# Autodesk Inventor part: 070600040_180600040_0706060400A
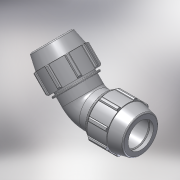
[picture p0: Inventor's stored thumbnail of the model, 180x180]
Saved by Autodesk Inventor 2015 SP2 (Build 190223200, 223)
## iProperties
Created: 2017-02
Part Number: 070600040_180600040_0706060400A
Material: PVC-Piping
Description: PLASSON 45° ELBOW 40-40
Document SubType Name: Modeling
Designer: KIM
Mass: 92.6774 g
Surface Area: 199.44 cm^2
Volume: 66.1981 cm^3
Density: 1.4 g/cm^3
Appearance: Smooth - White
Author: KIM
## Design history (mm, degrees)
derived "07060.ipt"
feature "Solid1::07060.ipt"
tag "TaggingFeature1"
body "Solid1"
other parameters: "d4" = 8.25, "d5" = 24.75, "d7" = 82, "d9" = 14.14286, "d11" = 3.3, "d13" = 120 deg, "d15" = 12 deg, "d16" = 71.34, "d18" = 2, "d19" = 35 deg, "d20" = 17.5 deg, "d21" = 76.26, "d23" = 0, "d25" = 360 deg, "d27" = 1.64, "d33" = 0.8, "d42" = 36.63, "d43" = 2.46, "d46" = 1.2, "d51" = 99, "d59" = 135 deg, "d63" = 84, "d67" = 61.5, "d68" = 3.3, "d72" = 1.5, "d73" = 0, "d74" = 0, "E_" = 82, "A_" = 99, "l_" = 84
